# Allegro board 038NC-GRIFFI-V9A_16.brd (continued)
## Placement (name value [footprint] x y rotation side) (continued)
UNK1TP_SDA  TP01  [TP_040_T]  19.67 330.46 0 top
UNK1TP_SHPHLD_F  TP01  [TP_040_T]  19.11 298.48 270 top
UNK1TP_SHPHLD_S  TP01  [TP_040_T]  19.11 295.94 90 top
UNK1TP_SW_F  TP01  [TP_040_T]  36.07 330.46 0 top
UNK1TP_SW_S  TP01  [TP_040_T]  33.53 330.46 0 top
UNK1TP_VBAT_F  TP01  [TP_040_T]  42.06 287.14 0 top
UNK1TP_VBAT_S  TP01  [TP_040_T]  38.86 287.14 0 top
UNK1TP_VBUS_F  TP01  [TP_040_T]  23.37 330.46 0 top
UNK1TP_VBUS_S  TP01  [TP_040_T]  25.91 330.46 0 top
UNK1TP_VDDIO_F  TP01  [TP_040_T]  38.61 335.54 0 top
UNK1TP_VDDIO_S  TP01  [TP_040_T]  125.91 486.88 0 top
UNK1TP_VEST  TP01  [TP_040_T]  13.28 269.26 0 top
UNK1TP_VOUT_F  TP01  [TP_040_T]  127.89 486.88 0 top
UNK1TP_VOUT_S  TP01  [TP_040_T]  38.61 330.46 0 top
UNK1TP_VSYS_F  TP01  [TP_040_T]  25.91 335.54 0 top
UNK1TP_VSYS_S  TP01  [TP_040_T]  23.37 335.54 0 top
UNK1U1  ADR4550BRZ-SOIC8  [SO8_195X127MM]  36.83 296.98 180 bottom
UNK2C1  1U-6.3-X7R-S6-MU  [C0603]  19.36 142.49 90 bottom
UNK2C2  2.2U-25-X8R-SA-TDK  [C1206]  35.84 178.21 180 bottom
UNK2C3  10U-6.3-X7R-S6-SS  [C0603]  31.92 177.36 270 bottom
UNK2C4  2.2U-25-X8R-SA-TDK  [C1206]  28.38 192.05 180 bottom
UNK2C5  2.2U-25-X8R-SA-TDK  [C1206]  22.68 192.05 0 bottom
UNK2C6  4.7U-6.3-X-S6  [C0603]  41.21 178.21 180 bottom
UNK2C7  0.1U-25-X7R-S6-YA  [C0603]  41.75 238.65 0 bottom
UNK2C8  1U-50-X7R-S6-TY  [C0603]  41.75 237.13 0 bottom
UNK2C9  0.1U-25-X7R-S6-YA  [C0603]  31.9 237.3 270 bottom
UNK2C12  2.2U-25-X8R-SA-TDK  [C1206]  26.98 142.89 90 bottom
UNK2CS1  CNC-S4  [C0402]  22.12 211.3 180 bottom
UNK2CS4  CNC-S4  [C0402]  22.12 207.49 0 bottom
UNK2CS5  CNC-S4  [C0402]  22.12 206.22 0 bottom
UNK2CS19  CNC-S4  [C0402]  35.85 207.02 0 bottom
UNK2CS20  CNC-S4  [C0402]  35.85 208.29 0 bottom
UNK2CS21  CNC-S4  [C0402]  35.85 209.56 0 bottom
UNK2CS22  CNC-S4  [C0402]  33.2 213.05 90 bottom
UNK2CS23  CNC-S4  [C0402]  31.93 213.05 90 bottom
UNK2CS25  CNC-S4  [C0402]  28.12 213.05 90 bottom
UNK2CS26  CNC-S4  [C0402]  26.85 213.05 270 bottom
UNK2CS27  CNC-S4  [C0402]  25.58 213.05 270 bottom
UNK2CS28  CNC-S4  [C0402]  24.31 213.05 90 bottom
UNK2K1  UA2-12NJ-V2  [RL_NECUA2_12V_V2]  33 185.33 90 bottom
UNK2K2  UA2-12NJ-V2  [RL_NECUA2_12V_V2]  25.53 185.33 90 bottom
UNK2K3  UA2-12NJ-V2  [RL_NECUA2_12V_V2]  16.66 207.46 270 bottom
UNK2K4  UA2-12NJ-V2  [RL_NECUA2_12V_V2]  25.53 169.7 90 bottom
UNK2K5  UA2-12NJ-V2  [RL_NECUA2_12V_V2]  18.07 169.7 90 bottom
UNK2K6  UA2-12NJ-V2  [RL_NECUA2_12V_V2]  33 169.3 270 bottom
UNK2K7  UA2-12NJ-V2  [RL_NECUA2_12V_V2]  40.46 169.7 90 bottom
UNK2K8  UA2-12NJ-V2  [RL_NECUA2_12V_V2]  18.07 185.33 90 bottom
UNK2K9  UA2-12NJ-V2  [RL_NECUA2_12V_V2]  40.46 142.72 270 bottom
UNK2K10  UA2-12NJ-V2  [RL_NECUA2_12V_V2]  40.46 185.33 90 bottom
UNK2K11  UA2-12NJ-V2  [RL_NECUA2_12V_V2]  33 229.98 90 bottom
UNK2K12  UA2-12NJ-V2  [RL_NECUA2_12V_V2]  40.46 229.98 90 bottom
UNK2K13  UA2-12NJ-V2  [RL_NECUA2_12V_V2]  18.07 229.58 270 bottom
UNK2K14  UA2-12NJ-V2  [RL_NECUA2_12V_V2]  25.53 229.58 270 bottom
UNK2R1  4.7K-1-S4-WA  [R0402]  16.51 201.49 180 bottom
UNK2R2  3.01K-0.1-S4-PAN  [R0402]  21.8 166.2 90 bottom
UNK2R3  10K-0.1-S4  [R0402]  29.26 172.8 270 bottom
UNK2R7  1K-1-S4  [R0402]  41.78 149.43 0 bottom
UNK2R8  1K-1-S4  [R0402]  39.14 149.43 180 bottom
UNK2R13  0-5-S4  [R0402]  164.24 484.56 0 top
UNK2R14  0-5-S4  [R0402]  166.44 484.56 0 top
UNK2R41  24K-0.1-S4  [R0402]  44.26 166.2 90 bottom
UNK2R42  44.2K-0.1-S4-PAN  [R0402]  44.26 168.4 90 bottom
UNK2RS1  0-5-S4  [R0402]  22.12 208.76 0 bottom
UNK2RS2  NC/0-5-S4  [R0402]  29.39 213.05 270 bottom
UNK2RS3  NC/0-5-S4  [R0402]  22.12 210.03 0 bottom
UNK2RS4  0-5-S4  [R0402]  30.66 213.05 270 bottom
UNK2RS5  0-5-S4  [R0402]  30.02 214.7 0 bottom
UNK2SH2  SHORT  [DEFAULT_SHORT_SMALL]  87.13 483.17 0 top
UNK2SH7  SHORT  [DEFAULT_SHORT_SMALL]  117.97 483.17 0 top
UNK2SH9  SHORT  [DEFAULT_SHORT_SMALL]  120.18 483.17 0 top
UNK2SH14  SHORT  [DEFAULT_SHORT_SMALL]  82.72 483.17 0 top
UNK2SH16  SHORT  [DEFAULT_SHORT_SMALL]  84.92 483.17 0 top
UNK2SH20  SHORT  [DEFAULT_SHORT_SMALL]  89.33 483.17 0 top
UNK2SH29  SHORT  [DEFAULT_SHORT_SMALL]  91.53 483.17 0 top
UNK2SH30  SHORT  [DEFAULT_SHORT_SMALL]  93.74 483.17 0 top
UNK2SH32  SHORT  [DEFAULT_SHORT_SMALL]  95.94 483.17 0 top
UNK2SH33  SHORT  [DEFAULT_SHORT_SMALL]  98.14 483.17 0 top
UNK2SH34  SHORT  [DEFAULT_SHORT_SMALL]  100.35 483.17 0 top
UNK2SH35  SHORT  [DEFAULT_SHORT_SMALL]  102.55 483.17 0 top
UNK2SH36  SHORT  [DEFAULT_SHORT_SMALL]  104.75 483.17 0 top
UNK2SH37  SHORT  [DEFAULT_SHORT_SMALL]  106.96 483.17 0 top
UNK2SH38  SHORT  [DEFAULT_SHORT_SMALL]  109.16 483.17 0 top
UNK2SH39  SHORT  [DEFAULT_SHORT_SMALL]  111.36 483.17 0 top
UNK2SH40  SHORT  [DEFAULT_SHORT_SMALL]  113.57 483.17 0 top
UNK2SH41  SHORT  [DEFAULT_SHORT_SMALL]  115.77 483.17 0 top
UNK2TP_AVSS2/TST  TP01  [TP_040_T]  13.84 214.45 0 top
UNK2TP_GPIO0  TP01  [TP_040_T]  29.17 178.59 270 top
UNK2TP_GPIO1  TP01  [TP_040_T]  29.17 176.05 90 top
UNK2TP_GPIO2  TP01  [TP_040_T]  16.47 178.59 180 top
UNK2TP_GPIO3  TP01  [TP_040_T]  16.47 176.05 90 top
UNK2TP_GPIO4  TP01  [TP_040_T]  19.01 178.59 90 top
UNK2TP_LED0  TP01  [TP_040_T]  21.55 176.05 90 top
UNK2TP_LED1  TP01  [TP_040_T]  21.55 178.59 270 top
UNK2TP_LED2  TP01  [TP_040_T]  19.01 176.05 90 top
UNK2TP_LSIN1_F  TP01  [TP_040_T]  26.98 146.72 180 top
UNK2TP_LSIN1_G  TP01  [TP_040_T]  22.89 486.88 0 top
UNK2TP_LSIN1_S  TP01  [TP_040_T]  29.52 146.72 180 top
UNK2TP_LSIN2/NCHGEN_F  TP01  [TP_040_T]  26.98 141.64 180 top
UNK2TP_LSIN2/NCHGEN_G  TP01  [TP_040_T]  24.87 486.88 0 top
UNK2TP_LSIN2/NCHGEN_S  TP01  [TP_040_T]  29.52 141.64 180 top
UNK2TP_LSOUT1_F  TP01  [TP_040_T]  26.85 486.88 0 top
UNK2TP_LSOUT1_G  TP01  [TP_040_T]  28.83 486.88 0 top
UNK2TP_LSOUT1_S  TP01  [TP_040_T]  24.09 176.05 90 top
UNK2TP_LSOUT2/SUSPEND1_G  TP01  [TP_040_T]  30.81 486.88 0 top
UNK2TP_LSOUT2/SUSPEND1_S  TP01  [TP_040_T]  24.09 178.59 180 top
UNK2TP_LSOUT2/SUSPEND_F  TP01  [TP_040_T]  32.79 486.88 0 top
UNK2TP_NCHG/ATB0_F  TP01  [TP_040_T]  23.93 233.58 0 top
UNK2TP_NCHG/ATB0_G  TP01  [TP_040_T]  23.93 229.18 0 top
UNK2TP_NCHG/ATB0_S  TP01  [TP_040_T]  27.13 231.38 0 top
UNK2TP_NPG/ATB1_F  TP01  [TP_040_T]  16.47 233.58 0 top
UNK2TP_NPG/ATB1_G  TP01  [TP_040_T]  16.47 229.18 0 top
UNK2TP_NPG/ATB1_S  TP01  [TP_040_T]  19.67 233.58 0 top
UNK2TP_NTC  TP01  [TP_040_T]  27.13 167.9 0 top
UNK2TP_REF_5V  TP01  [TP_040_T]  34.77 486.88 0 top
UNK2TP_SCL  TP01  [TP_040_T]  42.06 144.52 180 top
UNK2TP_SDA  TP01  [TP_040_T]  38.86 144.52 180 top
UNK2TP_SHPHLD_F  TP01  [TP_040_T]  26.63 176.05 90 top
UNK2TP_SHPHLD_S  TP01  [TP_040_T]  26.63 178.59 270 top
UNK2TP_SW_F  TP01  [TP_040_T]  21.9 146.72 180 top
UNK2TP_SW_S  TP01  [TP_040_T]  24.44 146.72 180 top
UNK2TP_VBAT_F  TP01  [TP_040_T]  42.06 228.18 0 top
UNK2TP_VBAT_S  TP01  [TP_040_T]  38.86 228.18 0 top
UNK2TP_VBUS_F  TP01  [TP_040_T]  34.6 146.72 180 top
UNK2TP_VBUS_S  TP01  [TP_040_T]  32.06 146.72 180 top
UNK2TP_VDDIO_F  TP01  [TP_040_T]  19.36 141.64 180 top
UNK2TP_VDDIO_S  TP01  [TP_040_T]  16.82 141.64 180 top
UNK2TP_VEST  TP01  [TP_040_T]  13.28 209.26 0 top
UNK2TP_VOUT_F  TP01  [TP_040_T]  16.82 146.72 180 top
UNK2TP_VOUT_S  TP01  [TP_040_T]  19.36 146.72 180 top
UNK2TP_VSYS_F  TP01  [TP_040_T]  32.06 141.64 180 top
UNK2TP_VSYS_S  TP01  [TP_040_T]  34.6 141.64 180 top
UNK2U1  ADR4550BRZ-SOIC8  [SO8_195X127MM]  36.32 238.02 180 bottom
UNK3C1  1U-6.3-X7R-S6-MU  [C0603]  68.61 334.69 270 bottom
UNK3C2  2.2U-25-X8R-SA-TDK  [C1206]  59.52 237.92 90 bottom
UNK3C3  10U-6.3-X7R-S6-SS  [C0603]  57.13 238.61 270 bottom
UNK3C4  2.2U-25-X8R-SA-TDK  [C1206]  49.67 237.92 90 bottom
UNK3C5  2.2U-25-X8R-SA-TDK  [C1206]  46.47 237.92 270 bottom
UNK3C6  4.7U-6.3-X-S6  [C0603]  74.26 241.42 270 bottom
UNK3C7  0.1U-25-X7R-S6-YA  [C0603]  72.25 297.61 0 bottom
UNK3C8  1U-50-X7R-S6-TY  [C0603]  72.25 296.09 0 bottom
UNK3C9  0.1U-25-X7R-S6-YA  [C0603]  62.41 296.26 270 bottom
UNK3C12  2.2U-25-X8R-SA-TDK  [C1206]  60.99 334.29 270 bottom
UNK3CS1  CNC-S4  [C0402]  52.12 271.3 180 bottom
UNK3CS4  CNC-S4  [C0402]  52.12 267.49 0 bottom
UNK3CS5  CNC-S4  [C0402]  52.12 266.22 0 bottom
UNK3CS19  CNC-S4  [C0402]  65.85 267.02 0 bottom
UNK3CS20  CNC-S4  [C0402]  65.85 268.29 0 bottom
UNK3CS21  CNC-S4  [C0402]  65.85 269.56 0 bottom
UNK3CS22  CNC-S4  [C0402]  63.2 273.05 90 bottom
UNK3CS23  CNC-S4  [C0402]  61.93 273.05 90 bottom
UNK3CS25  CNC-S4  [C0402]  58.12 273.05 90 bottom
UNK3CS26  CNC-S4  [C0402]  56.85 273.05 270 bottom
UNK3CS27  CNC-S4  [C0402]  55.58 273.05 270 bottom
UNK3CS28  CNC-S4  [C0402]  54.31 273.05 90 bottom
UNK3K1  UA2-12NJ-V2  [RL_NECUA2_12V_V2]  63 246.27 90 bottom
UNK3K2  UA2-12NJ-V2  [RL_NECUA2_12V_V2]  55.53 246.27 90 bottom
UNK3K3  UA2-12NJ-V2  [RL_NECUA2_12V_V2]  46.66 267.46 270 bottom
UNK3K4  UA2-12NJ-V2  [RL_NECUA2_12V_V2]  63 305.28 270 bottom
UNK3K5  UA2-12NJ-V2  [RL_NECUA2_12V_V2]  70.46 305.28 270 bottom
UNK3K6  UA2-12NJ-V2  [RL_NECUA2_12V_V2]  55.53 305.68 90 bottom
UNK3K7  UA2-12NJ-V2  [RL_NECUA2_12V_V2]  48.07 305.28 270 bottom
UNK3K8  UA2-12NJ-V2  [RL_NECUA2_12V_V2]  48.07 246.27 90 bottom
UNK3K9  UA2-12NJ-V2  [RL_NECUA2_12V_V2]  48.07 332.26 90 bottom
UNK3K10  UA2-12NJ-V2  [RL_NECUA2_12V_V2]  63 288.94 90 bottom
UNK3K11  UA2-12NJ-V2  [RL_NECUA2_12V_V2]  70.46 246.27 90 bottom
UNK3K12  UA2-12NJ-V2  [RL_NECUA2_12V_V2]  70.46 288.94 90 bottom
UNK3K13  UA2-12NJ-V2  [RL_NECUA2_12V_V2]  48.07 288.54 270 bottom
UNK3K14  UA2-12NJ-V2  [RL_NECUA2_12V_V2]  55.53 288.54 270 bottom
UNK3R1  4.7K-1-S4-WA  [R0402]  46.51 261.49 180 bottom
UNK3R2  3.01K-0.1-S4-PAN  [R0402]  66.73 308.78 270 bottom
UNK3R3  10K-0.1-S4  [R0402]  59.26 301.18 270 bottom
UNK3R7  1K-1-S4  [R0402]  46.75 325.55 180 bottom
UNK3R8  1K-1-S4  [R0402]  49.39 325.55 0 bottom
UNK3R13  0-5-S4  [R0402]  168.65 484.56 0 top
UNK3R14  0-5-S4  [R0402]  170.85 484.56 0 top
UNK3R41  24K-0.1-S4  [R0402]  44.26 308.78 270 bottom
UNK3R42  44.2K-0.1-S4-PAN  [R0402]  44.26 306.58 270 bottom
UNK3RS1  0-5-S4  [R0402]  52.12 268.76 0 bottom
UNK3RS2  NC/0-5-S4  [R0402]  59.39 273.05 270 bottom
UNK3RS3  NC/0-5-S4  [R0402]  52.12 270.03 0 bottom
UNK3RS4  0-5-S4  [R0402]  60.66 273.05 270 bottom
UNK3RS5  0-5-S4  [R0402]  60.02 274.7 0 bottom
UNK3SH2  SHORT  [DEFAULT_SHORT_SMALL]  126.79 483.17 0 top
UNK3SH7  SHORT  [DEFAULT_SHORT_SMALL]  157.63 483.17 0 top
UNK3SH9  SHORT  [DEFAULT_SHORT_SMALL]  159.83 483.17 0 top
UNK3SH14  SHORT  [DEFAULT_SHORT_SMALL]  122.38 483.17 0 top
UNK3SH16  SHORT  [DEFAULT_SHORT_SMALL]  124.58 483.17 0 top
UNK3SH20  SHORT  [DEFAULT_SHORT_SMALL]  128.99 483.17 0 top
UNK3SH29  SHORT  [DEFAULT_SHORT_SMALL]  131.19 483.17 0 top
UNK3SH30  SHORT  [DEFAULT_SHORT_SMALL]  133.39 483.17 0 top
UNK3SH32  SHORT  [DEFAULT_SHORT_SMALL]  135.6 483.17 0 top
UNK3SH33  SHORT  [DEFAULT_SHORT_SMALL]  137.8 483.17 0 top
UNK3SH34  SHORT  [DEFAULT_SHORT_SMALL]  140 483.17 0 top
UNK3SH35  SHORT  [DEFAULT_SHORT_SMALL]  142.21 483.17 0 top
UNK3SH36  SHORT  [DEFAULT_SHORT_SMALL]  144.41 483.17 0 top
UNK3SH37  SHORT  [DEFAULT_SHORT_SMALL]  146.61 483.17 0 top
UNK3SH38  SHORT  [DEFAULT_SHORT_SMALL]  148.82 483.17 0 top
UNK3SH39  SHORT  [DEFAULT_SHORT_SMALL]  151.02 483.17 0 top
UNK3SH40  SHORT  [DEFAULT_SHORT_SMALL]  153.22 483.17 0 top
UNK3SH41  SHORT  [DEFAULT_SHORT_SMALL]  155.43 483.17 0 top
UNK3TP_AVSS2/TST  TP01  [TP_040_T]  43.84 274.45 0 top
UNK3TP_GPIO0  TP01  [TP_040_T]  46.57 295.94 90 top
UNK3TP_GPIO1  TP01  [TP_040_T]  46.57 298.48 270 top
UNK3TP_GPIO2  TP01  [TP_040_T]  59.27 295.94 0 top
UNK3TP_GPIO3  TP01  [TP_040_T]  59.27 298.48 270 top
UNK3TP_GPIO4  TP01  [TP_040_T]  56.73 295.94 270 top
UNK3TP_LED0  TP01  [TP_040_T]  54.19 298.48 270 top
UNK3TP_LED1  TP01  [TP_040_T]  54.19 295.94 90 top
UNK3TP_LED2  TP01  [TP_040_T]  56.73 298.48 270 top
UNK3TP_LSIN1_F  TP01  [TP_040_T]  60.99 330.46 0 top
UNK3TP_LSIN1_G  TP01  [TP_040_T]  36.75 486.88 0 top
UNK3TP_LSIN1_S  TP01  [TP_040_T]  58.45 330.46 0 top
UNK3TP_LSIN2/NCHGEN_F  TP01  [TP_040_T]  60.99 335.54 0 top
UNK3TP_LSIN2/NCHGEN_G  TP01  [TP_040_T]  38.74 486.88 0 top
UNK3TP_LSIN2/NCHGEN_S  TP01  [TP_040_T]  58.45 335.54 0 top
UNK3TP_LSOUT1_F  TP01  [TP_040_T]  49.67 244.47 180 top
UNK3TP_LSOUT1_G  TP01  [TP_040_T]  40.72 486.88 0 top
UNK3TP_LSOUT1_S  TP01  [TP_040_T]  51.65 298.48 270 top
UNK3TP_LSOUT2/SUSPEND1_G  TP01  [TP_040_T]  42.7 486.88 0 top
UNK3TP_LSOUT2/SUSPEND1_S  TP01  [TP_040_T]  51.65 295.94 0 top
UNK3TP_LSOUT2/SUSPEND_F  TP01  [TP_040_T]  68.86 244.47 180 top
UNK3TP_NCHG/ATB0_F  TP01  [TP_040_T]  53.93 292.54 0 top
UNK3TP_NCHG/ATB0_G  TP01  [TP_040_T]  53.93 288.14 0 top
UNK3TP_NCHG/ATB0_S  TP01  [TP_040_T]  57.13 290.34 0 top
UNK3TP_NPG/ATB1_F  TP01  [TP_040_T]  46.47 292.54 0 top
UNK3TP_NPG/ATB1_G  TP01  [TP_040_T]  46.47 288.14 0 top
UNK3TP_NPG/ATB1_S  TP01  [TP_040_T]  49.67 292.54 0 top
UNK3TP_NTC  TP01  [TP_040_T]  61.4 307.08 180 top
UNK3TP_REF_5V  TP01  [TP_040_T]  64.59 242.27 180 top
UNK3TP_SCL  TP01  [TP_040_T]  46.47 330.46 0 top
UNK3TP_SDA  TP01  [TP_040_T]  49.67 330.46 0 top
UNK3TP_SHPHLD_F  TP01  [TP_040_T]  49.11 298.48 270 top
UNK3TP_SHPHLD_S  TP01  [TP_040_T]  49.11 295.94 90 top
UNK3TP_SW_F  TP01  [TP_040_T]  66.07 330.46 0 top
UNK3TP_SW_S  TP01  [TP_040_T]  63.53 330.46 0 top
UNK3TP_VBAT_F  TP01  [TP_040_T]  72.06 287.14 0 top
UNK3TP_VBAT_S  TP01  [TP_040_T]  68.86 287.14 0 top
UNK3TP_VBUS_F  TP01  [TP_040_T]  53.37 330.46 0 top
UNK3TP_VBUS_S  TP01  [TP_040_T]  55.91 330.46 0 top
UNK3TP_VDDIO_F  TP01  [TP_040_T]  68.61 335.54 0 top
UNK3TP_VDDIO_S  TP01  [TP_040_T]  44.68 486.88 0 top
UNK3TP_VEST  TP01  [TP_040_T]  43.28 269.26 0 top
UNK3TP_VOUT_F  TP01  [TP_040_T]  46.66 486.88 0 top
UNK3TP_VOUT_S  TP01  [TP_040_T]  68.61 330.46 0 top
UNK3TP_VSYS_F  TP01  [TP_040_T]  55.91 335.54 0 top
UNK3TP_VSYS_S  TP01  [TP_040_T]  53.37 335.54 0 top
UNK3U1  ADR4550BRZ-SOIC8  [SO8_195X127MM]  66.83 296.98 180 bottom
UNK4C1  1U-6.3-X7R-S6-MU  [C0603]  49.36 142.49 90 bottom
UNK4C2  2.2U-25-X8R-SA-TDK  [C1206]  65.84 178.21 180 bottom
UNK4C3  10U-6.3-X7R-S6-SS  [C0603]  61.92 177.36 270 bottom
UNK4C4  2.2U-25-X8R-SA-TDK  [C1206]  58.38 192.05 180 bottom
UNK4C5  2.2U-25-X8R-SA-TDK  [C1206]  52.68 192.05 0 bottom
UNK4C6  4.7U-6.3-X-S6  [C0603]  71.21 178.21 180 bottom
UNK4C7  0.1U-25-X7R-S6-YA  [C0603]  71.75 238.65 0 bottom
UNK4C8  1U-50-X7R-S6-TY  [C0603]  71.75 237.13 0 bottom
UNK4C9  0.1U-25-X7R-S6-YA  [C0603]  61.9 237.3 270 bottom
UNK4C12  2.2U-25-X8R-SA-TDK  [C1206]  56.98 142.89 90 bottom
UNK4CS1  CNC-S4  [C0402]  52.12 211.3 180 bottom
UNK4CS4  CNC-S4  [C0402]  52.12 207.49 0 bottom
UNK4CS5  CNC-S4  [C0402]  52.12 206.22 0 bottom
UNK4CS19  CNC-S4  [C0402]  65.85 207.02 0 bottom
UNK4CS20  CNC-S4  [C0402]  65.85 208.29 0 bottom
UNK4CS21  CNC-S4  [C0402]  65.85 209.56 0 bottom
UNK4CS22  CNC-S4  [C0402]  63.2 213.05 90 bottom
UNK4CS23  CNC-S4  [C0402]  61.93 213.05 90 bottom
UNK4CS25  CNC-S4  [C0402]  58.12 213.05 90 bottom
UNK4CS26  CNC-S4  [C0402]  56.85 213.05 270 bottom
UNK4CS27  CNC-S4  [C0402]  55.58 213.05 270 bottom
UNK4CS28  CNC-S4  [C0402]  54.31 213.05 90 bottom
UNK4K1  UA2-12NJ-V2  [RL_NECUA2_12V_V2]  63 185.33 90 bottom
UNK4K2  UA2-12NJ-V2  [RL_NECUA2_12V_V2]  55.53 185.33 90 bottom
UNK4K3  UA2-12NJ-V2  [RL_NECUA2_12V_V2]  46.66 207.46 270 bottom
UNK4K4  UA2-12NJ-V2  [RL_NECUA2_12V_V2]  55.53 169.7 90 bottom
UNK4K5  UA2-12NJ-V2  [RL_NECUA2_12V_V2]  48.07 169.7 90 bottom
UNK4K6  UA2-12NJ-V2  [RL_NECUA2_12V_V2]  63 169.3 270 bottom
UNK4K7  UA2-12NJ-V2  [RL_NECUA2_12V_V2]  70.46 169.7 90 bottom
UNK4K8  UA2-12NJ-V2  [RL_NECUA2_12V_V2]  48.07 185.33 90 bottom
UNK4K9  UA2-12NJ-V2  [RL_NECUA2_12V_V2]  70.46 142.72 270 bottom
UNK4K10  UA2-12NJ-V2  [RL_NECUA2_12V_V2]  70.46 185.33 90 bottom
UNK4K11  UA2-12NJ-V2  [RL_NECUA2_12V_V2]  63 229.98 90 bottom
UNK4K12  UA2-12NJ-V2  [RL_NECUA2_12V_V2]  70.46 229.98 90 bottom
UNK4K13  UA2-12NJ-V2  [RL_NECUA2_12V_V2]  48.07 229.58 270 bottom
UNK4K14  UA2-12NJ-V2  [RL_NECUA2_12V_V2]  55.53 229.58 270 bottom
UNK4R1  4.7K-1-S4-WA  [R0402]  46.51 201.49 180 bottom
UNK4R2  3.01K-0.1-S4-PAN  [R0402]  51.8 166.2 90 bottom
UNK4R3  10K-0.1-S4  [R0402]  59.26 172.8 270 bottom
UNK4R7  1K-1-S4  [R0402]  71.78 149.43 0 bottom
UNK4R8  1K-1-S4  [R0402]  69.14 149.43 180 bottom
UNK4R13  0-5-S4  [R0402]  173.05 484.56 0 top
UNK4R14  0-5-S4  [R0402]  175.26 484.56 0 top
UNK4R41  24K-0.1-S4  [R0402]  74.26 166.2 90 bottom
UNK4R42  44.2K-0.1-S4-PAN  [R0402]  74.26 168.4 90 bottom
UNK4RS1  0-5-S4  [R0402]  52.12 208.76 0 bottom
UNK4RS2  NC/0-5-S4  [R0402]  59.39 213.05 270 bottom
UNK4RS3  NC/0-5-S4  [R0402]  52.12 210.03 0 bottom
UNK4RS4  0-5-S4  [R0402]  60.66 213.05 270 bottom
UNK4RS5  0-5-S4  [R0402]  60.02 214.7 0 bottom
UNK4SH2  SHORT  [DEFAULT_SHORT_SMALL]  166.44 483.17 0 top
UNK4SH7  SHORT  [DEFAULT_SHORT_SMALL]  197.29 483.17 0 top
UNK4SH9  SHORT  [DEFAULT_SHORT_SMALL]  199.49 483.17 0 top
UNK4SH14  SHORT  [DEFAULT_SHORT_SMALL]  162.04 483.17 0 top
UNK4SH16  SHORT  [DEFAULT_SHORT_SMALL]  164.24 483.17 0 top
UNK4SH20  SHORT  [DEFAULT_SHORT_SMALL]  168.65 483.17 0 top
UNK4SH29  SHORT  [DEFAULT_SHORT_SMALL]  170.85 483.17 0 top
UNK4SH30  SHORT  [DEFAULT_SHORT_SMALL]  173.05 483.17 0 top
UNK4SH32  SHORT  [DEFAULT_SHORT_SMALL]  175.26 483.17 0 top
UNK4SH33  SHORT  [DEFAULT_SHORT_SMALL]  177.46 483.17 0 top
UNK4SH34  SHORT  [DEFAULT_SHORT_SMALL]  179.66 483.17 0 top
UNK4SH35  SHORT  [DEFAULT_SHORT_SMALL]  181.87 483.17 0 top
UNK4SH36  SHORT  [DEFAULT_SHORT_SMALL]  184.07 483.17 0 top
UNK4SH37  SHORT  [DEFAULT_SHORT_SMALL]  186.27 483.17 0 top
UNK4SH38  SHORT  [DEFAULT_SHORT_SMALL]  188.47 483.17 0 top
UNK4SH39  SHORT  [DEFAULT_SHORT_SMALL]  190.68 483.17 0 top
UNK4SH40  SHORT  [DEFAULT_SHORT_SMALL]  192.88 483.17 0 top
UNK4SH41  SHORT  [DEFAULT_SHORT_SMALL]  195.08 483.17 0 top
UNK4TP_AVSS2/TST  TP01  [TP_040_T]  43.84 214.45 0 top
UNK4TP_GPIO0  TP01  [TP_040_T]  59.17 178.59 270 top
UNK4TP_GPIO1  TP01  [TP_040_T]  59.17 176.05 90 top
UNK4TP_GPIO2  TP01  [TP_040_T]  46.47 178.59 180 top
UNK4TP_GPIO3  TP01  [TP_040_T]  46.47 176.05 90 top
UNK4TP_GPIO4  TP01  [TP_040_T]  49.01 178.59 90 top
UNK4TP_LED0  TP01  [TP_040_T]  51.55 176.05 90 top
UNK4TP_LED1  TP01  [TP_040_T]  51.55 178.59 270 top
UNK4TP_LED2  TP01  [TP_040_T]  49.01 176.05 90 top
UNK4TP_LSIN1_F  TP01  [TP_040_T]  56.98 146.72 180 top
UNK4TP_LSIN1_G  TP01  [TP_040_T]  48.64 486.88 0 top
UNK4TP_LSIN1_S  TP01  [TP_040_T]  59.52 146.72 180 top
UNK4TP_LSIN2/NCHGEN_F  TP01  [TP_040_T]  56.98 141.64 180 top
UNK4TP_LSIN2/NCHGEN_G  TP01  [TP_040_T]  50.62 486.88 0 top
UNK4TP_LSIN2/NCHGEN_S  TP01  [TP_040_T]  59.52 141.64 180 top
UNK4TP_LSOUT1_F  TP01  [TP_040_T]  52.6 486.88 0 top
UNK4TP_LSOUT1_G  TP01  [TP_040_T]  54.58 486.88 0 top
UNK4TP_LSOUT1_S  TP01  [TP_040_T]  54.09 176.05 90 top
UNK4TP_LSOUT2/SUSPEND1_G  TP01  [TP_040_T]  56.57 486.88 0 top
UNK4TP_LSOUT2/SUSPEND1_S  TP01  [TP_040_T]  54.09 178.59 180 top
UNK4TP_LSOUT2/SUSPEND_F  TP01  [TP_040_T]  58.55 486.88 0 top
UNK4TP_NCHG/ATB0_F  TP01  [TP_040_T]  53.93 233.58 0 top
UNK4TP_NCHG/ATB0_G  TP01  [TP_040_T]  53.93 229.18 0 top
UNK4TP_NCHG/ATB0_S  TP01  [TP_040_T]  57.13 231.38 0 top
UNK4TP_NPG/ATB1_F  TP01  [TP_040_T]  46.47 233.58 0 top
UNK4TP_NPG/ATB1_G  TP01  [TP_040_T]  46.47 229.18 0 top
UNK4TP_NPG/ATB1_S  TP01  [TP_040_T]  49.67 233.58 0 top
UNK4TP_NTC  TP01  [TP_040_T]  57.13 167.9 0 top
UNK4TP_REF_5V  TP01  [TP_040_T]  60.53 486.88 0 top
UNK4TP_SCL  TP01  [TP_040_T]  72.06 144.52 180 top
UNK4TP_SDA  TP01  [TP_040_T]  68.86 144.52 180 top
UNK4TP_SHPHLD_F  TP01  [TP_040_T]  56.63 176.05 90 top
UNK4TP_SHPHLD_S  TP01  [TP_040_T]  56.63 178.59 270 top
UNK4TP_SW_F  TP01  [TP_040_T]  51.9 146.72 180 top
UNK4TP_SW_S  TP01  [TP_040_T]  54.44 146.72 180 top
UNK4TP_VBAT_F  TP01  [TP_040_T]  72.06 228.18 0 top
UNK4TP_VBAT_S  TP01  [TP_040_T]  68.86 228.18 0 top
UNK4TP_VBUS_F  TP01  [TP_040_T]  64.6 146.72 180 top
UNK4TP_VBUS_S  TP01  [TP_040_T]  62.06 146.72 180 top
UNK4TP_VDDIO_F  TP01  [TP_040_T]  49.36 141.64 180 top
UNK4TP_VDDIO_S  TP01  [TP_040_T]  46.82 141.64 180 top
UNK4TP_VEST  TP01  [TP_040_T]  43.28 209.26 0 top
UNK4TP_VOUT_F  TP01  [TP_040_T]  46.82 146.72 180 top
UNK4TP_VOUT_S  TP01  [TP_040_T]  49.36 146.72 180 top
UNK4TP_VSYS_F  TP01  [TP_040_T]  62.06 141.64 180 top
UNK4TP_VSYS_S  TP01  [TP_040_T]  64.6 141.64 180 top
UNK4U1  ADR4550BRZ-SOIC8  [SO8_195X127MM]  66.32 238.02 180 bottom
UNK5C1  1U-6.3-X7R-S6-MU  [C0603]  98.61 334.69 270 bottom
UNK5C2  2.2U-25-X8R-SA-TDK  [C1206]  89.52 237.92 90 bottom
UNK5C3  10U-6.3-X7R-S6-SS  [C0603]  87.13 238.61 270 bottom
UNK5C4  2.2U-25-X8R-SA-TDK  [C1206]  79.67 237.92 90 bottom
UNK5C5  2.2U-25-X8R-SA-TDK  [C1206]  76.47 237.92 270 bottom
UNK5C6  4.7U-6.3-X-S6  [C0603]  104.26 241.42 270 bottom
UNK5C7  0.1U-25-X7R-S6-YA  [C0603]  102.25 297.61 0 bottom
UNK5C8  1U-50-X7R-S6-TY  [C0603]  102.25 296.09 0 bottom
UNK5C9  0.1U-25-X7R-S6-YA  [C0603]  92.41 296.26 270 bottom
UNK5C12  2.2U-25-X8R-SA-TDK  [C1206]  90.99 334.29 270 bottom
UNK5CS1  CNC-S4  [C0402]  82.12 271.3 180 bottom
UNK5CS4  CNC-S4  [C0402]  82.12 267.49 0 bottom
UNK5CS5  CNC-S4  [C0402]  82.12 266.22 0 bottom
UNK5CS19  CNC-S4  [C0402]  95.85 267.02 0 bottom
UNK5CS20  CNC-S4  [C0402]  95.85 268.29 0 bottom
UNK5CS21  CNC-S4  [C0402]  95.85 269.56 0 bottom
UNK5CS22  CNC-S4  [C0402]  93.2 273.05 90 bottom
UNK5CS23  CNC-S4  [C0402]  91.93 273.05 90 bottom
UNK5CS25  CNC-S4  [C0402]  88.12 273.05 90 bottom
UNK5CS26  CNC-S4  [C0402]  86.85 273.05 270 bottom
UNK5CS27  CNC-S4  [C0402]  85.58 273.05 270 bottom
UNK5CS28  CNC-S4  [C0402]  84.31 273.05 90 bottom
UNK5K1  UA2-12NJ-V2  [RL_NECUA2_12V_V2]  92.99 246.27 90 bottom
UNK5K2  UA2-12NJ-V2  [RL_NECUA2_12V_V2]  85.53 246.27 90 bottom
UNK5K3  UA2-12NJ-V2  [RL_NECUA2_12V_V2]  76.66 267.46 270 bottom
UNK5K4  UA2-12NJ-V2  [RL_NECUA2_12V_V2]  92.99 305.28 270 bottom
UNK5K5  UA2-12NJ-V2  [RL_NECUA2_12V_V2]  100.46 305.28 270 bottom
UNK5K6  UA2-12NJ-V2  [RL_NECUA2_12V_V2]  85.53 305.68 90 bottom
UNK5K7  UA2-12NJ-V2  [RL_NECUA2_12V_V2]  78.07 305.28 270 bottom
UNK5K8  UA2-12NJ-V2  [RL_NECUA2_12V_V2]  78.07 246.27 90 bottom
UNK5K9  UA2-12NJ-V2  [RL_NECUA2_12V_V2]  78.07 332.26 90 bottom
UNK5K10  UA2-12NJ-V2  [RL_NECUA2_12V_V2]  92.99 288.94 90 bottom
UNK5K11  UA2-12NJ-V2  [RL_NECUA2_12V_V2]  100.46 246.27 90 bottom
UNK5K12  UA2-12NJ-V2  [RL_NECUA2_12V_V2]  100.46 288.94 90 bottom
UNK5K13  UA2-12NJ-V2  [RL_NECUA2_12V_V2]  78.07 288.54 270 bottom
UNK5K14  UA2-12NJ-V2  [RL_NECUA2_12V_V2]  85.53 288.54 270 bottom
UNK5R1  4.7K-1-S4-WA  [R0402]  76.51 261.49 180 bottom
UNK5R2  3.01K-0.1-S4-PAN  [R0402]  96.73 308.78 270 bottom
UNK5R3  10K-0.1-S4  [R0402]  89.26 301.18 270 bottom
UNK5R7  1K-1-S4  [R0402]  76.75 325.55 180 bottom
UNK5R8  1K-1-S4  [R0402]  79.39 325.55 0 bottom
UNK5R13  0-5-S4  [R0402]  177.46 484.56 0 top
UNK5R14  0-5-S4  [R0402]  179.66 484.56 0 top
UNK5R41  24K-0.1-S4  [R0402]  74.26 308.78 270 bottom
UNK5R42  44.2K-0.1-S4-PAN  [R0402]  74.26 306.58 270 bottom
UNK5RS1  0-5-S4  [R0402]  82.12 268.76 0 bottom
UNK5RS2  NC/0-5-S4  [R0402]  89.39 273.05 270 bottom
UNK5RS3  NC/0-5-S4  [R0402]  82.12 270.03 0 bottom
UNK5RS4  0-5-S4  [R0402]  90.66 273.05 270 bottom
UNK5RS5  0-5-S4  [R0402]  90.02 274.7 0 bottom
UNK5SH2  SHORT  [DEFAULT_SHORT_SMALL]  206.1 483.17 0 top
UNK5SH7  SHORT  [DEFAULT_SHORT_SMALL]  236.95 483.17 0 top
UNK5SH9  SHORT  [DEFAULT_SHORT_SMALL]  239.15 483.17 0 top
UNK5SH14  SHORT  [DEFAULT_SHORT_SMALL]  201.69 483.17 0 top
UNK5SH16  SHORT  [DEFAULT_SHORT_SMALL]  203.9 483.17 0 top
UNK5SH20  SHORT  [DEFAULT_SHORT_SMALL]  208.3 483.17 0 top
UNK5SH29  SHORT  [DEFAULT_SHORT_SMALL]  210.51 483.17 0 top
UNK5SH30  SHORT  [DEFAULT_SHORT_SMALL]  212.71 483.17 0 top
UNK5SH32  SHORT  [DEFAULT_SHORT_SMALL]  214.91 483.17 0 top
UNK5SH33  SHORT  [DEFAULT_SHORT_SMALL]  217.12 483.17 0 top
UNK5SH34  SHORT  [DEFAULT_SHORT_SMALL]  219.32 483.17 0 top
UNK5SH35  SHORT  [DEFAULT_SHORT_SMALL]  221.52 483.17 0 top
UNK5SH36  SHORT  [DEFAULT_SHORT_SMALL]  223.73 483.17 0 top
UNK5SH37  SHORT  [DEFAULT_SHORT_SMALL]  225.93 483.17 0 top
UNK5SH38  SHORT  [DEFAULT_SHORT_SMALL]  228.13 483.17 0 top
UNK5SH39  SHORT  [DEFAULT_SHORT_SMALL]  230.34 483.17 0 top
UNK5SH40  SHORT  [DEFAULT_SHORT_SMALL]  232.54 483.17 0 top
UNK5SH41  SHORT  [DEFAULT_SHORT_SMALL]  234.74 483.17 0 top
UNK5TP_AVSS2/TST  TP01  [TP_040_T]  73.84 274.45 0 top
UNK5TP_GPIO0  TP01  [TP_040_T]  76.57 295.94 90 top
UNK5TP_GPIO1  TP01  [TP_040_T]  76.57 298.48 270 top
UNK5TP_GPIO2  TP01  [TP_040_T]  89.27 295.94 0 top
UNK5TP_GPIO3  TP01  [TP_040_T]  89.27 298.48 270 top
UNK5TP_GPIO4  TP01  [TP_040_T]  86.73 295.94 270 top
UNK5TP_LED0  TP01  [TP_040_T]  84.19 298.48 270 top
UNK5TP_LED1  TP01  [TP_040_T]  84.19 295.94 90 top
UNK5TP_LED2  TP01  [TP_040_T]  86.73 298.48 270 top
UNK5TP_LSIN1_F  TP01  [TP_040_T]  90.99 330.46 0 top
UNK5TP_LSIN1_G  TP01  [TP_040_T]  62.51 486.88 0 top
UNK5TP_LSIN1_S  TP01  [TP_040_T]  88.45 330.46 0 top
UNK5TP_LSIN2/NCHGEN_F  TP01  [TP_040_T]  90.99 335.54 0 top
UNK5TP_LSIN2/NCHGEN_G  TP01  [TP_040_T]  64.49 486.88 0 top
UNK5TP_LSIN2/NCHGEN_S  TP01  [TP_040_T]  88.45 335.54 0 top
UNK5TP_LSOUT1_F  TP01  [TP_040_T]  79.67 244.47 180 top
UNK5TP_LSOUT1_G  TP01  [TP_040_T]  66.47 486.88 0 top
UNK5TP_LSOUT1_S  TP01  [TP_040_T]  81.65 298.48 270 top
UNK5TP_LSOUT2/SUSPEND1_G  TP01  [TP_040_T]  68.45 486.88 0 top
UNK5TP_LSOUT2/SUSPEND1_S  TP01  [TP_040_T]  81.65 295.94 0 top
UNK5TP_LSOUT2/SUSPEND_F  TP01  [TP_040_T]  98.86 244.47 180 top
UNK5TP_NCHG/ATB0_F  TP01  [TP_040_T]  83.93 292.54 0 top
UNK5TP_NCHG/ATB0_G  TP01  [TP_040_T]  83.93 288.14 0 top
UNK5TP_NCHG/ATB0_S  TP01  [TP_040_T]  87.13 290.34 0 top
UNK5TP_NPG/ATB1_F  TP01  [TP_040_T]  76.47 292.54 0 top
UNK5TP_NPG/ATB1_G  TP01  [TP_040_T]  76.47 288.14 0 top
UNK5TP_NPG/ATB1_S  TP01  [TP_040_T]  79.67 292.54 0 top
UNK5TP_NTC  TP01  [TP_040_T]  91.4 307.08 180 top
UNK5TP_REF_5V  TP01  [TP_040_T]  94.59 242.27 180 top
UNK5TP_SCL  TP01  [TP_040_T]  76.47 330.46 0 top
UNK5TP_SDA  TP01  [TP_040_T]  79.67 330.46 0 top
UNK5TP_SHPHLD_F  TP01  [TP_040_T]  79.11 298.48 270 top
UNK5TP_SHPHLD_S  TP01  [TP_040_T]  79.11 295.94 90 top
UNK5TP_SW_F  TP01  [TP_040_T]  96.07 330.46 0 top
UNK5TP_SW_S  TP01  [TP_040_T]  93.53 330.46 0 top
UNK5TP_VBAT_F  TP01  [TP_040_T]  102.06 287.14 0 top
UNK5TP_VBAT_S  TP01  [TP_040_T]  98.86 287.14 0 top
UNK5TP_VBUS_F  TP01  [TP_040_T]  83.37 330.46 0 top
UNK5TP_VBUS_S  TP01  [TP_040_T]  85.91 330.46 0 top
UNK5TP_VDDIO_F  TP01  [TP_040_T]  98.61 335.54 0 top
UNK5TP_VDDIO_S  TP01  [TP_040_T]  70.43 486.88 0 top
UNK5TP_VEST  TP01  [TP_040_T]  73.28 269.26 0 top
UNK5TP_VOUT_F  TP01  [TP_040_T]  72.42 486.88 0 top
UNK5TP_VOUT_S  TP01  [TP_040_T]  98.61 330.46 0 top
UNK5TP_VSYS_F  TP01  [TP_040_T]  85.91 335.54 0 top
UNK5TP_VSYS_S  TP01  [TP_040_T]  83.37 335.54 0 top
UNK5U1  ADR4550BRZ-SOIC8  [SO8_195X127MM]  96.83 296.98 180 bottom
UNK6C1  1U-6.3-X7R-S6-MU  [C0603]  79.36 142.49 90 bottom
UNK6C2  2.2U-25-X8R-SA-TDK  [C1206]  95.84 178.21 180 bottom
UNK6C3  10U-6.3-X7R-S6-SS  [C0603]  91.92 177.36 270 bottom
UNK6C4  2.2U-25-X8R-SA-TDK  [C1206]  88.38 192.05 180 bottom
UNK6C5  2.2U-25-X8R-SA-TDK  [C1206]  82.68 192.05 0 bottom
UNK6C6  4.7U-6.3-X-S6  [C0603]  101.21 178.21 180 bottom
UNK6C7  0.1U-25-X7R-S6-YA  [C0603]  101.75 238.65 0 bottom
UNK6C8  1U-50-X7R-S6-TY  [C0603]  101.75 237.13 0 bottom
UNK6C9  0.1U-25-X7R-S6-YA  [C0603]  91.9 237.3 270 bottom
UNK6C12  2.2U-25-X8R-SA-TDK  [C1206]  86.98 142.89 90 bottom
UNK6CS1  CNC-S4  [C0402]  82.12 211.3 180 bottom
UNK6CS4  CNC-S4  [C0402]  82.12 207.49 0 bottom
UNK6CS5  CNC-S4  [C0402]  82.12 206.22 0 bottom
UNK6CS19  CNC-S4  [C0402]  95.85 207.02 0 bottom
UNK6CS20  CNC-S4  [C0402]  95.85 208.29 0 bottom
UNK6CS21  CNC-S4  [C0402]  95.85 209.56 0 bottom
UNK6CS22  CNC-S4  [C0402]  93.2 213.05 90 bottom
UNK6CS23  CNC-S4  [C0402]  91.93 213.05 90 bottom
UNK6CS25  CNC-S4  [C0402]  88.12 213.05 90 bottom
UNK6CS26  CNC-S4  [C0402]  86.85 213.05 270 bottom
UNK6CS27  CNC-S4  [C0402]  85.58 213.05 270 bottom
UNK6CS28  CNC-S4  [C0402]  84.31 213.05 90 bottom
UNK6K1  UA2-12NJ-V2  [RL_NECUA2_12V_V2]  92.99 185.33 90 bottom
UNK6K2  UA2-12NJ-V2  [RL_NECUA2_12V_V2]  85.53 185.33 90 bottom
UNK6K3  UA2-12NJ-V2  [RL_NECUA2_12V_V2]  76.66 207.46 270 bottom
UNK6K4  UA2-12NJ-V2  [RL_NECUA2_12V_V2]  85.53 169.7 90 bottom
UNK6K5  UA2-12NJ-V2  [RL_NECUA2_12V_V2]  78.07 169.7 90 bottom
UNK6K6  UA2-12NJ-V2  [RL_NECUA2_12V_V2]  92.99 169.3 270 bottom
UNK6K7  UA2-12NJ-V2  [RL_NECUA2_12V_V2]  100.46 169.7 90 bottom
UNK6K8  UA2-12NJ-V2  [RL_NECUA2_12V_V2]  78.07 185.33 90 bottom
UNK6K9  UA2-12NJ-V2  [RL_NECUA2_12V_V2]  100.46 142.72 270 bottom
UNK6K10  UA2-12NJ-V2  [RL_NECUA2_12V_V2]  100.46 185.33 90 bottom
UNK6K11  UA2-12NJ-V2  [RL_NECUA2_12V_V2]  92.99 229.98 90 bottom
UNK6K12  UA2-12NJ-V2  [RL_NECUA2_12V_V2]  100.46 229.98 90 bottom
UNK6K13  UA2-12NJ-V2  [RL_NECUA2_12V_V2]  78.07 229.58 270 bottom
UNK6K14  UA2-12NJ-V2  [RL_NECUA2_12V_V2]  85.53 229.58 270 bottom
UNK6R1  4.7K-1-S4-WA  [R0402]  76.51 201.49 180 bottom
UNK6R2  3.01K-0.1-S4-PAN  [R0402]  81.8 166.2 90 bottom
UNK6R3  10K-0.1-S4  [R0402]  89.26 172.8 270 bottom
UNK6R7  1K-1-S4  [R0402]  101.78 149.43 0 bottom
UNK6R8  1K-1-S4  [R0402]  99.14 149.43 180 bottom
UNK6R13  0-5-S4  [R0402]  181.87 484.56 0 top
UNK6R14  0-5-S4  [R0402]  184.07 484.56 0 top
UNK6R41  24K-0.1-S4  [R0402]  104.26 166.2 90 bottom
UNK6R42  44.2K-0.1-S4-PAN  [R0402]  104.26 168.4 90 bottom
UNK6RS1  0-5-S4  [R0402]  82.12 208.76 0 bottom
UNK6RS2  NC/0-5-S4  [R0402]  89.39 213.05 270 bottom
UNK6RS3  NC/0-5-S4  [R0402]  82.12 210.03 0 bottom
UNK6RS4  0-5-S4  [R0402]  90.66 213.05 270 bottom
UNK6RS5  0-5-S4  [R0402]  90.02 214.7 0 bottom
UNK6SH2  SHORT  [DEFAULT_SHORT_SMALL]  245.76 483.17 0 top
UNK6SH7  SHORT  [DEFAULT_SHORT_SMALL]  10.02 484.64 0 top
UNK6SH9  SHORT  [DEFAULT_SHORT_SMALL]  12.22 484.64 0 top
UNK6SH14  SHORT  [DEFAULT_SHORT_SMALL]  241.35 483.17 0 top
UNK6SH16  SHORT  [DEFAULT_SHORT_SMALL]  243.55 483.17 0 top
UNK6SH20  SHORT  [DEFAULT_SHORT_SMALL]  68.73 475.82 0 top
UNK6SH29  SHORT  [DEFAULT_SHORT_SMALL]  250.16 483.17 0 top
UNK6SH30  SHORT  [DEFAULT_SHORT_SMALL]  252.37 483.17 0 top
UNK6SH32  SHORT  [DEFAULT_SHORT_SMALL]  254.57 483.17 0 top
UNK6SH33  SHORT  [DEFAULT_SHORT_SMALL]  256.77 483.17 0 top
UNK6SH34  SHORT  [DEFAULT_SHORT_SMALL]  258.98 483.17 0 top
UNK6SH35  SHORT  [DEFAULT_SHORT_SMALL]  261.18 483.17 0 top
UNK6SH36  SHORT  [DEFAULT_SHORT_SMALL]  263.38 483.17 0 top
UNK6SH37  SHORT  [DEFAULT_SHORT_SMALL]  265.59 483.17 0 top
UNK6SH38  SHORT  [DEFAULT_SHORT_SMALL]  1.2 484.64 0 top
UNK6SH39  SHORT  [DEFAULT_SHORT_SMALL]  3.41 484.64 0 top
UNK6SH40  SHORT  [DEFAULT_SHORT_SMALL]  5.61 484.64 0 top
UNK6SH41  SHORT  [DEFAULT_SHORT_SMALL]  7.81 484.64 0 top
UNK6TP_AVSS2/TST  TP01  [TP_040_T]  73.84 214.45 0 top
UNK6TP_GPIO0  TP01  [TP_040_T]  89.17 178.59 270 top
UNK6TP_GPIO1  TP01  [TP_040_T]  89.17 176.05 90 top
UNK6TP_GPIO2  TP01  [TP_040_T]  76.47 178.59 180 top
UNK6TP_GPIO3  TP01  [TP_040_T]  76.47 176.05 90 top
UNK6TP_GPIO4  TP01  [TP_040_T]  79.01 178.59 90 top
UNK6TP_LED0  TP01  [TP_040_T]  81.55 176.05 90 top
UNK6TP_LED1  TP01  [TP_040_T]  81.55 178.59 270 top
UNK6TP_LED2  TP01  [TP_040_T]  79.01 176.05 90 top
UNK6TP_LSIN1_F  TP01  [TP_040_T]  86.98 146.72 180 top
UNK6TP_LSIN1_G  TP01  [TP_040_T]  74.4 486.88 0 top
UNK6TP_LSIN1_S  TP01  [TP_040_T]  89.52 146.72 180 top
UNK6TP_LSIN2/NCHGEN_F  TP01  [TP_040_T]  86.98 141.64 180 top
UNK6TP_LSIN2/NCHGEN_G  TP01  [TP_040_T]  76.38 486.88 0 top
UNK6TP_LSIN2/NCHGEN_S  TP01  [TP_040_T]  89.52 141.64 180 top
UNK6TP_LSOUT1_F  TP01  [TP_040_T]  78.36 486.88 0 top
UNK6TP_LSOUT1_G  TP01  [TP_040_T]  80.34 486.88 0 top
UNK6TP_LSOUT1_S  TP01  [TP_040_T]  84.09 176.05 90 top
UNK6TP_LSOUT2/SUSPEND1_G  TP01  [TP_040_T]  82.32 486.88 0 top
UNK6TP_LSOUT2/SUSPEND1_S  TP01  [TP_040_T]  84.09 178.59 180 top
UNK6TP_LSOUT2/SUSPEND_F  TP01  [TP_040_T]  84.3 486.88 0 top
UNK6TP_NCHG/ATB0_F  TP01  [TP_040_T]  83.93 233.58 0 top
UNK6TP_NCHG/ATB0_G  TP01  [TP_040_T]  83.93 229.18 0 top
UNK6TP_NCHG/ATB0_S  TP01  [TP_040_T]  87.13 231.38 0 top
UNK6TP_NPG/ATB1_F  TP01  [TP_040_T]  76.47 233.58 0 top
UNK6TP_NPG/ATB1_G  TP01  [TP_040_T]  76.47 229.18 0 top
UNK6TP_NPG/ATB1_S  TP01  [TP_040_T]  79.67 233.58 0 top
UNK6TP_NTC  TP01  [TP_040_T]  87.13 167.9 0 top
UNK6TP_REF_5V  TP01  [TP_040_T]  86.28 486.88 0 top
UNK6TP_SCL  TP01  [TP_040_T]  102.06 144.52 180 top
UNK6TP_SDA  TP01  [TP_040_T]  98.86 144.52 180 top
UNK6TP_SHPHLD_F  TP01  [TP_040_T]  86.63 176.05 90 top
UNK6TP_SHPHLD_S  TP01  [TP_040_T]  86.63 178.59 270 top
UNK6TP_SW_F  TP01  [TP_040_T]  81.9 146.72 180 top
UNK6TP_SW_S  TP01  [TP_040_T]  84.44 146.72 180 top
UNK6TP_VBAT_F  TP01  [TP_040_T]  102.06 228.18 0 top
UNK6TP_VBAT_S  TP01  [TP_040_T]  98.86 228.18 0 top
UNK6TP_VBUS_F  TP01  [TP_040_T]  94.6 146.72 180 top
UNK6TP_VBUS_S  TP01  [TP_040_T]  92.06 146.72 180 top
UNK6TP_VDDIO_F  TP01  [TP_040_T]  79.36 141.64 180 top
UNK6TP_VDDIO_S  TP01  [TP_040_T]  76.82 141.64 180 top
UNK6TP_VEST  TP01  [TP_040_T]  73.28 209.26 0 top
UNK6TP_VOUT_F  TP01  [TP_040_T]  76.82 146.72 180 top
UNK6TP_VOUT_S  TP01  [TP_040_T]  79.36 146.72 180 top
UNK6TP_VSYS_F  TP01  [TP_040_T]  92.06 141.64 180 top
UNK6TP_VSYS_S  TP01  [TP_040_T]  94.6 141.64 180 top
UNK6U1  ADR4550BRZ-SOIC8  [SO8_195X127MM]  96.32 238.02 180 bottom
UNK7C1  1U-6.3-X7R-S6-MU  [C0603]  128.61 334.69 270 bottom
UNK7C2  2.2U-25-X8R-SA-TDK  [C1206]  119.52 237.92 90 bottom
UNK7C3  10U-6.3-X7R-S6-SS  [C0603]  117.13 238.61 270 bottom
UNK7C4  2.2U-25-X8R-SA-TDK  [C1206]  109.67 237.92 90 bottom
UNK7C5  2.2U-25-X8R-SA-TDK  [C1206]  106.47 237.92 270 bottom
UNK7C6  4.7U-6.3-X-S6  [C0603]  134.26 241.42 270 bottom
UNK7C7  0.1U-25-X7R-S6-YA  [C0603]  132.25 297.61 0 bottom
UNK7C8  1U-50-X7R-S6-TY  [C0603]  132.25 296.09 0 bottom
UNK7C9  0.1U-25-X7R-S6-YA  [C0603]  122.41 296.26 270 bottom
UNK7C12  2.2U-25-X8R-SA-TDK  [C1206]  120.99 334.29 270 bottom
UNK7CS1  CNC-S4  [C0402]  112.12 271.3 180 bottom
UNK7CS4  CNC-S4  [C0402]  112.12 267.49 0 bottom
UNK7CS5  CNC-S4  [C0402]  112.12 266.22 0 bottom
UNK7CS19  CNC-S4  [C0402]  125.85 267.02 0 bottom
UNK7CS20  CNC-S4  [C0402]  125.85 268.29 0 bottom
UNK7CS21  CNC-S4  [C0402]  125.85 269.56 0 bottom
UNK7CS22  CNC-S4  [C0402]  123.2 273.05 90 bottom
UNK7CS23  CNC-S4  [C0402]  121.93 273.05 90 bottom
UNK7CS25  CNC-S4  [C0402]  118.12 273.05 90 bottom
UNK7CS26  CNC-S4  [C0402]  116.85 273.05 270 bottom
UNK7CS27  CNC-S4  [C0402]  115.58 273.05 270 bottom
UNK7CS28  CNC-S4  [C0402]  114.31 273.05 90 bottom
UNK7K1  UA2-12NJ-V2  [RL_NECUA2_12V_V2]  122.99 246.27 90 bottom
UNK7K2  UA2-12NJ-V2  [RL_NECUA2_12V_V2]  115.53 246.27 90 bottom
UNK7K3  UA2-12NJ-V2  [RL_NECUA2_12V_V2]  106.66 267.46 270 bottom
UNK7K4  UA2-12NJ-V2  [RL_NECUA2_12V_V2]  122.99 305.28 270 bottom
UNK7K5  UA2-12NJ-V2  [RL_NECUA2_12V_V2]  130.46 305.28 270 bottom
UNK7K6  UA2-12NJ-V2  [RL_NECUA2_12V_V2]  115.53 305.68 90 bottom
UNK7K7  UA2-12NJ-V2  [RL_NECUA2_12V_V2]  108.07 305.28 270 bottom
UNK7K8  UA2-12NJ-V2  [RL_NECUA2_12V_V2]  108.07 246.27 90 bottom
UNK7K9  UA2-12NJ-V2  [RL_NECUA2_12V_V2]  108.07 332.26 90 bottom
UNK7K10  UA2-12NJ-V2  [RL_NECUA2_12V_V2]  122.99 288.94 90 bottom
UNK7K11  UA2-12NJ-V2  [RL_NECUA2_12V_V2]  130.46 246.27 90 bottom
UNK7K12  UA2-12NJ-V2  [RL_NECUA2_12V_V2]  130.46 288.94 90 bottom
UNK7K13  UA2-12NJ-V2  [RL_NECUA2_12V_V2]  108.07 288.54 270 bottom
UNK7K14  UA2-12NJ-V2  [RL_NECUA2_12V_V2]  115.53 288.54 270 bottom
UNK7R1  4.7K-1-S4-WA  [R0402]  106.51 261.49 180 bottom
UNK7R2  3.01K-0.1-S4-PAN  [R0402]  126.73 308.78 270 bottom
UNK7R3  10K-0.1-S4  [R0402]  119.26 301.18 270 bottom
UNK7R7  1K-1-S4  [R0402]  106.75 325.55 180 bottom
UNK7R8  1K-1-S4  [R0402]  109.39 325.55 0 bottom
UNK7R13  0-5-S4  [R0402]  186.27 484.56 0 top
UNK7R14  0-5-S4  [R0402]  188.47 484.56 0 top
UNK7R41  24K-0.1-S4  [R0402]  104.26 308.78 270 bottom
UNK7R42  44.2K-0.1-S4-PAN  [R0402]  104.26 306.58 270 bottom
UNK7RS1  0-5-S4  [R0402]  112.12 268.76 0 bottom
UNK7RS2  NC/0-5-S4  [R0402]  119.39 273.05 270 bottom
UNK7RS3  NC/0-5-S4  [R0402]  112.12 270.03 0 bottom
UNK7RS4  0-5-S4  [R0402]  120.66 273.05 270 bottom
UNK7RS5  0-5-S4  [R0402]  120.02 274.7 0 bottom
UNK7SH2  SHORT  [DEFAULT_SHORT_SMALL]  18.83 484.64 0 top
UNK7SH7  SHORT  [DEFAULT_SHORT_SMALL]  49.67 484.64 0 top
UNK7SH9  SHORT  [DEFAULT_SHORT_SMALL]  51.88 484.64 0 top
UNK7SH14  SHORT  [DEFAULT_SHORT_SMALL]  14.42 484.64 0 top
UNK7SH16  SHORT  [DEFAULT_SHORT_SMALL]  16.63 484.64 0 top
UNK7SH20  SHORT  [DEFAULT_SHORT_SMALL]  21.03 484.64 0 top
UNK7SH29  SHORT  [DEFAULT_SHORT_SMALL]  23.24 484.64 0 top
UNK7SH30  SHORT  [DEFAULT_SHORT_SMALL]  25.44 484.64 0 top
UNK7SH32  SHORT  [DEFAULT_SHORT_SMALL]  27.64 484.64 0 top
UNK7SH33  SHORT  [DEFAULT_SHORT_SMALL]  29.84 484.64 0 top
UNK7SH34  SHORT  [DEFAULT_SHORT_SMALL]  32.05 484.64 0 top
UNK7SH35  SHORT  [DEFAULT_SHORT_SMALL]  34.25 484.64 0 top
UNK7SH36  SHORT  [DEFAULT_SHORT_SMALL]  36.45 484.64 0 top
UNK7SH37  SHORT  [DEFAULT_SHORT_SMALL]  38.66 484.64 0 top
UNK7SH38  SHORT  [DEFAULT_SHORT_SMALL]  40.86 484.64 0 top
UNK7SH39  SHORT  [DEFAULT_SHORT_SMALL]  43.06 484.64 0 top
UNK7SH40  SHORT  [DEFAULT_SHORT_SMALL]  45.27 484.64 0 top
UNK7SH41  SHORT  [DEFAULT_SHORT_SMALL]  47.47 484.64 0 top
UNK7TP_AVSS2/TST  TP01  [TP_040_T]  103.84 274.45 0 top
UNK7TP_GPIO0  TP01  [TP_040_T]  106.57 295.94 90 top
UNK7TP_GPIO1  TP01  [TP_040_T]  106.57 298.48 270 top
UNK7TP_GPIO2  TP01  [TP_040_T]  119.27 295.94 0 top
UNK7TP_GPIO3  TP01  [TP_040_T]  119.27 298.48 270 top
UNK7TP_GPIO4  TP01  [TP_040_T]  116.73 295.94 270 top
UNK7TP_LED0  TP01  [TP_040_T]  114.19 298.48 270 top
UNK7TP_LED1  TP01  [TP_040_T]  114.19 295.94 90 top
UNK7TP_LED2  TP01  [TP_040_T]  116.73 298.48 270 top
UNK7TP_LSIN1_F  TP01  [TP_040_T]  120.99 330.46 0 top
UNK7TP_LSIN1_G  TP01  [TP_040_T]  88.27 486.88 0 top
UNK7TP_LSIN1_S  TP01  [TP_040_T]  118.45 330.46 0 top
UNK7TP_LSIN2/NCHGEN_F  TP01  [TP_040_T]  120.99 335.54 0 top
UNK7TP_LSIN2/NCHGEN_G  TP01  [TP_040_T]  90.25 486.88 0 top
UNK7TP_LSIN2/NCHGEN_S  TP01  [TP_040_T]  118.45 335.54 0 top
UNK7TP_LSOUT1_F  TP01  [TP_040_T]  109.67 244.47 180 top
UNK7TP_LSOUT1_G  TP01  [TP_040_T]  92.23 486.88 0 top
UNK7TP_LSOUT1_S  TP01  [TP_040_T]  111.65 298.48 270 top
UNK7TP_LSOUT2/SUSPEND1_G  TP01  [TP_040_T]  94.21 486.88 0 top
UNK7TP_LSOUT2/SUSPEND1_S  TP01  [TP_040_T]  111.65 295.94 0 top
UNK7TP_LSOUT2/SUSPEND_F  TP01  [TP_040_T]  128.86 244.47 180 top
UNK7TP_NCHG/ATB0_F  TP01  [TP_040_T]  113.93 292.54 0 top
UNK7TP_NCHG/ATB0_G  TP01  [TP_040_T]  113.93 288.14 0 top
UNK7TP_NCHG/ATB0_S  TP01  [TP_040_T]  117.13 290.34 0 top
UNK7TP_NPG/ATB1_F  TP01  [TP_040_T]  106.47 292.54 0 top
UNK7TP_NPG/ATB1_G  TP01  [TP_040_T]  106.47 288.14 0 top
UNK7TP_NPG/ATB1_S  TP01  [TP_040_T]  109.67 292.54 0 top
UNK7TP_NTC  TP01  [TP_040_T]  121.39 307.08 180 top
UNK7TP_REF_5V  TP01  [TP_040_T]  124.59 242.27 180 top
UNK7TP_SCL  TP01  [TP_040_T]  106.47 330.46 0 top
UNK7TP_SDA  TP01  [TP_040_T]  109.67 330.46 0 top
UNK7TP_SHPHLD_F  TP01  [TP_040_T]  109.11 298.48 270 top
UNK7TP_SHPHLD_S  TP01  [TP_040_T]  109.11 295.94 90 top
UNK7TP_SW_F  TP01  [TP_040_T]  126.07 330.46 0 top
UNK7TP_SW_S  TP01  [TP_040_T]  123.53 330.46 0 top
UNK7TP_VBAT_F  TP01  [TP_040_T]  132.06 287.14 0 top
UNK7TP_VBAT_S  TP01  [TP_040_T]  128.86 287.14 0 top
UNK7TP_VBUS_F  TP01  [TP_040_T]  113.37 330.46 0 top
UNK7TP_VBUS_S  TP01  [TP_040_T]  115.91 330.46 0 top
UNK7TP_VDDIO_F  TP01  [TP_040_T]  128.61 335.54 0 top
UNK7TP_VDDIO_S  TP01  [TP_040_T]  96.19 486.88 0 top
UNK7TP_VEST  TP01  [TP_040_T]  103.28 269.26 0 top
UNK7TP_VOUT_F  TP01  [TP_040_T]  98.17 486.88 0 top
UNK7TP_VOUT_S  TP01  [TP_040_T]  128.61 330.46 0 top
UNK7TP_VSYS_F  TP01  [TP_040_T]  115.91 335.54 0 top
UNK7TP_VSYS_S  TP01  [TP_040_T]  113.37 335.54 0 top
UNK7U1  ADR4550BRZ-SOIC8  [SO8_195X127MM]  126.83 296.98 180 bottom
UNK8C1  1U-6.3-X7R-S6-MU  [C0603]  109.36 142.49 90 bottom
UNK8C2  2.2U-25-X8R-SA-TDK  [C1206]  125.84 178.21 180 bottom
UNK8C3  10U-6.3-X7R-S6-SS  [C0603]  121.92 177.36 270 bottom
UNK8C4  2.2U-25-X8R-SA-TDK  [C1206]  118.38 192.05 180 bottom
UNK8C5  2.2U-25-X8R-SA-TDK  [C1206]  112.68 192.05 0 bottom
UNK8C6  4.7U-6.3-X-S6  [C0603]  131.21 178.21 180 bottom
UNK8C7  0.1U-25-X7R-S6-YA  [C0603]  131.75 238.65 0 bottom
UNK8C8  1U-50-X7R-S6-TY  [C0603]  131.75 237.13 0 bottom
UNK8C9  0.1U-25-X7R-S6-YA  [C0603]  121.9 237.3 270 bottom
UNK8C12  2.2U-25-X8R-SA-TDK  [C1206]  116.98 142.89 90 bottom
UNK8CS1  CNC-S4  [C0402]  112.12 211.3 180 bottom
UNK8CS4  CNC-S4  [C0402]  112.12 207.49 0 bottom
UNK8CS5  CNC-S4  [C0402]  112.12 206.22 0 bottom
UNK8CS19  CNC-S4  [C0402]  125.85 207.02 0 bottom
UNK8CS20  CNC-S4  [C0402]  125.85 208.29 0 bottom
UNK8CS21  CNC-S4  [C0402]  125.85 209.56 0 bottom
UNK8CS22  CNC-S4  [C0402]  123.2 213.05 90 bottom
UNK8CS23  CNC-S4  [C0402]  121.93 213.05 90 bottom
UNK8CS25  CNC-S4  [C0402]  118.12 213.05 90 bottom
UNK8CS26  CNC-S4  [C0402]  116.85 213.05 270 bottom
UNK8CS27  CNC-S4  [C0402]  115.58 213.05 270 bottom
UNK8CS28  CNC-S4  [C0402]  114.31 213.05 90 bottom
UNK8K1  UA2-12NJ-V2  [RL_NECUA2_12V_V2]  122.99 185.33 90 bottom
UNK8K2  UA2-12NJ-V2  [RL_NECUA2_12V_V2]  115.53 185.33 90 bottom
UNK8K3  UA2-12NJ-V2  [RL_NECUA2_12V_V2]  106.66 207.46 270 bottom
UNK8K4  UA2-12NJ-V2  [RL_NECUA2_12V_V2]  115.53 169.7 90 bottom
UNK8K5  UA2-12NJ-V2  [RL_NECUA2_12V_V2]  108.07 169.7 90 bottom
UNK8K6  UA2-12NJ-V2  [RL_NECUA2_12V_V2]  122.99 169.3 270 bottom
UNK8K7  UA2-12NJ-V2  [RL_NECUA2_12V_V2]  130.46 169.7 90 bottom
UNK8K8  UA2-12NJ-V2  [RL_NECUA2_12V_V2]  108.07 185.33 90 bottom
UNK8K9  UA2-12NJ-V2  [RL_NECUA2_12V_V2]  130.46 142.72 270 bottom
UNK8K10  UA2-12NJ-V2  [RL_NECUA2_12V_V2]  130.46 185.33 90 bottom
UNK8K11  UA2-12NJ-V2  [RL_NECUA2_12V_V2]  122.99 229.98 90 bottom
UNK8K12  UA2-12NJ-V2  [RL_NECUA2_12V_V2]  130.46 229.98 90 bottom
UNK8K13  UA2-12NJ-V2  [RL_NECUA2_12V_V2]  108.07 229.58 270 bottom
UNK8K14  UA2-12NJ-V2  [RL_NECUA2_12V_V2]  115.53 229.58 270 bottom
UNK8R1  4.7K-1-S4-WA  [R0402]  106.51 201.49 180 bottom
UNK8R2  3.01K-0.1-S4-PAN  [R0402]  111.8 166.2 90 bottom
UNK8R3  10K-0.1-S4  [R0402]  119.26 172.8 270 bottom
UNK8R7  1K-1-S4  [R0402]  131.78 149.43 0 bottom
UNK8R8  1K-1-S4  [R0402]  129.14 149.43 180 bottom
UNK8R13  0-5-S4  [R0402]  190.68 484.56 0 top
UNK8R14  0-5-S4  [R0402]  192.88 484.56 0 top
UNK8R41  24K-0.1-S4  [R0402]  134.26 166.2 90 bottom
UNK8R42  44.2K-0.1-S4-PAN  [R0402]  134.26 168.4 90 bottom
UNK8RS1  0-5-S4  [R0402]  112.12 208.76 0 bottom
UNK8RS2  NC/0-5-S4  [R0402]  119.39 213.05 270 bottom
UNK8RS3  NC/0-5-S4  [R0402]  112.12 210.03 0 bottom
UNK8RS4  0-5-S4  [R0402]  120.66 213.05 270 bottom
UNK8RS5  0-5-S4  [R0402]  120.02 214.7 0 bottom
UNK8SH2  SHORT  [DEFAULT_SHORT_SMALL]  58.49 484.64 0 top
UNK8SH7  SHORT  [DEFAULT_SHORT_SMALL]  89.33 484.64 0 top
UNK8SH9  SHORT  [DEFAULT_SHORT_SMALL]  91.53 484.64 0 top
UNK8SH14  SHORT  [DEFAULT_SHORT_SMALL]  54.08 484.64 0 top
UNK8SH16  SHORT  [DEFAULT_SHORT_SMALL]  56.28 484.64 0 top
UNK8SH20  SHORT  [DEFAULT_SHORT_SMALL]  60.69 484.64 0 top
UNK8SH29  SHORT  [DEFAULT_SHORT_SMALL]  62.89 484.64 0 top
UNK8SH30  SHORT  [DEFAULT_SHORT_SMALL]  65.1 484.64 0 top
UNK8SH32  SHORT  [DEFAULT_SHORT_SMALL]  67.3 484.64 0 top
UNK8SH33  SHORT  [DEFAULT_SHORT_SMALL]  69.5 484.64 0 top
UNK8SH34  SHORT  [DEFAULT_SHORT_SMALL]  71.71 484.64 0 top
UNK8SH35  SHORT  [DEFAULT_SHORT_SMALL]  73.91 484.64 0 top
UNK8SH36  SHORT  [DEFAULT_SHORT_SMALL]  76.11 484.64 0 top
UNK8SH37  SHORT  [DEFAULT_SHORT_SMALL]  78.32 484.64 0 top
UNK8SH38  SHORT  [DEFAULT_SHORT_SMALL]  80.52 484.64 0 top
UNK8SH39  SHORT  [DEFAULT_SHORT_SMALL]  82.72 484.64 0 top
UNK8SH40  SHORT  [DEFAULT_SHORT_SMALL]  84.92 484.64 0 top
UNK8SH41  SHORT  [DEFAULT_SHORT_SMALL]  87.13 484.64 0 top
UNK8TP_AVSS2/TST  TP01  [TP_040_T]  103.84 214.45 0 top
UNK8TP_GPIO0  TP01  [TP_040_T]  119.17 178.59 270 top
UNK8TP_GPIO1  TP01  [TP_040_T]  119.17 176.05 90 top
UNK8TP_GPIO2  TP01  [TP_040_T]  106.47 178.59 180 top
UNK8TP_GPIO3  TP01  [TP_040_T]  106.47 176.05 90 top
UNK8TP_GPIO4  TP01  [TP_040_T]  109.01 178.59 90 top
UNK8TP_LED0  TP01  [TP_040_T]  111.55 176.05 90 top
UNK8TP_LED1  TP01  [TP_040_T]  111.55 178.59 270 top
UNK8TP_LED2  TP01  [TP_040_T]  109.01 176.05 90 top
UNK8TP_LSIN1_F  TP01  [TP_040_T]  116.98 146.72 180 top
UNK8TP_LSIN1_G  TP01  [TP_040_T]  100.15 486.88 0 top
UNK8TP_LSIN1_S  TP01  [TP_040_T]  119.52 146.72 180 top
UNK8TP_LSIN2/NCHGEN_F  TP01  [TP_040_T]  116.98 141.64 180 top
UNK8TP_LSIN2/NCHGEN_G  TP01  [TP_040_T]  102.13 486.88 0 top
UNK8TP_LSIN2/NCHGEN_S  TP01  [TP_040_T]  119.52 141.64 180 top
UNK8TP_LSOUT1_F  TP01  [TP_040_T]  104.11 486.88 0 top
UNK8TP_LSOUT1_G  TP01  [TP_040_T]  106.1 486.88 0 top
UNK8TP_LSOUT1_S  TP01  [TP_040_T]  114.09 176.05 90 top
UNK8TP_LSOUT2/SUSPEND1_G  TP01  [TP_040_T]  108.08 486.88 0 top
UNK8TP_LSOUT2/SUSPEND1_S  TP01  [TP_040_T]  114.09 178.59 180 top
UNK8TP_LSOUT2/SUSPEND_F  TP01  [TP_040_T]  110.06 486.88 0 top
UNK8TP_NCHG/ATB0_F  TP01  [TP_040_T]  113.93 233.58 0 top
UNK8TP_NCHG/ATB0_G  TP01  [TP_040_T]  113.93 229.18 0 top
UNK8TP_NCHG/ATB0_S  TP01  [TP_040_T]  117.13 231.38 0 top
UNK8TP_NPG/ATB1_F  TP01  [TP_040_T]  106.47 233.58 0 top
UNK8TP_NPG/ATB1_G  TP01  [TP_040_T]  106.47 229.18 0 top
UNK8TP_NPG/ATB1_S  TP01  [TP_040_T]  109.67 233.58 0 top
UNK8TP_NTC  TP01  [TP_040_T]  117.13 167.9 0 top
UNK8TP_REF_5V  TP01  [TP_040_T]  112.04 486.88 0 top
UNK8TP_SCL  TP01  [TP_040_T]  132.06 144.52 180 top
UNK8TP_SDA  TP01  [TP_040_T]  128.86 144.52 180 top
UNK8TP_SHPHLD_F  TP01  [TP_040_T]  116.63 176.05 90 top
UNK8TP_SHPHLD_S  TP01  [TP_040_T]  116.63 178.59 270 top
UNK8TP_SW_F  TP01  [TP_040_T]  111.9 146.72 180 top
UNK8TP_SW_S  TP01  [TP_040_T]  114.44 146.72 180 top
UNK8TP_VBAT_F  TP01  [TP_040_T]  132.06 228.18 0 top
UNK8TP_VBAT_S  TP01  [TP_040_T]  128.86 228.18 0 top
UNK8TP_VBUS_F  TP01  [TP_040_T]  124.6 146.72 180 top
UNK8TP_VBUS_S  TP01  [TP_040_T]  122.06 146.72 180 top
UNK8TP_VDDIO_F  TP01  [TP_040_T]  109.36 141.64 180 top
UNK8TP_VDDIO_S  TP01  [TP_040_T]  106.82 141.64 180 top
UNK8TP_VEST  TP01  [TP_040_T]  103.28 209.26 0 top
UNK8TP_VOUT_F  TP01  [TP_040_T]  106.82 146.72 180 top
UNK8TP_VOUT_S  TP01  [TP_040_T]  109.36 146.72 180 top
UNK8TP_VSYS_F  TP01  [TP_040_T]  122.06 141.64 180 top
UNK8TP_VSYS_S  TP01  [TP_040_T]  124.6 141.64 180 top
UNK8U1  ADR4550BRZ-SOIC8  [SO8_195X127MM]  126.32 238.02 180 bottom
UNK9C1  1U-6.3-X7R-S6-MU  [C0603]  158.61 334.69 270 bottom
UNK9C2  2.2U-25-X8R-SA-TDK  [C1206]  149.52 237.92 90 bottom
UNK9C3  10U-6.3-X7R-S6-SS  [C0603]  147.13 238.61 270 bottom
UNK9C4  2.2U-25-X8R-SA-TDK  [C1206]  139.67 237.92 90 bottom
UNK9C5  2.2U-25-X8R-SA-TDK  [C1206]  136.47 237.92 270 bottom
UNK9C6  4.7U-6.3-X-S6  [C0603]  164.26 241.42 270 bottom
UNK9C7  0.1U-25-X7R-S6-YA  [C0603]  162.25 297.61 0 bottom
UNK9C8  1U-50-X7R-S6-TY  [C0603]  162.25 296.09 0 bottom
UNK9C9  0.1U-25-X7R-S6-YA  [C0603]  152.41 296.26 270 bottom
UNK9C12  2.2U-25-X8R-SA-TDK  [C1206]  150.99 334.29 270 bottom
UNK9CS1  CNC-S4  [C0402]  142.12 271.3 180 bottom
UNK9CS4  CNC-S4  [C0402]  142.12 267.49 0 bottom
UNK9CS5  CNC-S4  [C0402]  142.12 266.22 0 bottom
UNK9CS19  CNC-S4  [C0402]  155.85 267.02 0 bottom
UNK9CS20  CNC-S4  [C0402]  155.85 268.29 0 bottom
UNK9CS21  CNC-S4  [C0402]  155.85 269.56 0 bottom
UNK9CS22  CNC-S4  [C0402]  153.2 273.05 90 bottom
UNK9CS23  CNC-S4  [C0402]  151.93 273.05 90 bottom
UNK9CS25  CNC-S4  [C0402]  148.12 273.05 90 bottom
UNK9CS26  CNC-S4  [C0402]  146.85 273.05 270 bottom
UNK9CS27  CNC-S4  [C0402]  145.58 273.05 270 bottom
UNK9CS28  CNC-S4  [C0402]  144.31 273.05 90 bottom
UNK9K1  UA2-12NJ-V2  [RL_NECUA2_12V_V2]  152.99 246.27 90 bottom
UNK9K2  UA2-12NJ-V2  [RL_NECUA2_12V_V2]  145.53 246.27 90 bottom
UNK9K3  UA2-12NJ-V2  [RL_NECUA2_12V_V2]  136.66 267.46 270 bottom
UNK9K4  UA2-12NJ-V2  [RL_NECUA2_12V_V2]  152.99 305.28 270 bottom
UNK9K5  UA2-12NJ-V2  [RL_NECUA2_12V_V2]  160.46 305.28 270 bottom
UNK9K6  UA2-12NJ-V2  [RL_NECUA2_12V_V2]  145.53 305.68 90 bottom
UNK9K7  UA2-12NJ-V2  [RL_NECUA2_12V_V2]  138.07 305.28 270 bottom
UNK9K8  UA2-12NJ-V2  [RL_NECUA2_12V_V2]  138.07 246.27 90 bottom
UNK9K9  UA2-12NJ-V2  [RL_NECUA2_12V_V2]  138.07 332.26 90 bottom
UNK9K10  UA2-12NJ-V2  [RL_NECUA2_12V_V2]  152.99 288.94 90 bottom
UNK9K11  UA2-12NJ-V2  [RL_NECUA2_12V_V2]  160.46 246.27 90 bottom
UNK9K12  UA2-12NJ-V2  [RL_NECUA2_12V_V2]  160.46 288.94 90 bottom
UNK9K13  UA2-12NJ-V2  [RL_NECUA2_12V_V2]  138.07 288.54 270 bottom
UNK9K14  UA2-12NJ-V2  [RL_NECUA2_12V_V2]  145.53 288.54 270 bottom
UNK9R1  4.7K-1-S4-WA  [R0402]  136.51 261.49 180 bottom
UNK9R2  3.01K-0.1-S4-PAN  [R0402]  156.73 308.78 270 bottom
UNK9R3  10K-0.1-S4  [R0402]  149.26 301.18 270 bottom
UNK9R7  1K-1-S4  [R0402]  136.75 325.55 180 bottom
UNK9R8  1K-1-S4  [R0402]  139.39 325.55 0 bottom
UNK9R13  0-5-S4  [R0402]  195.08 484.56 0 top
UNK9R14  0-5-S4  [R0402]  247.96 483.08 0 top
UNK9R41  24K-0.1-S4  [R0402]  134.26 308.78 270 bottom
UNK9R42  44.2K-0.1-S4-PAN  [R0402]  134.26 306.58 270 bottom
UNK9RS1  0-5-S4  [R0402]  142.12 268.76 0 bottom
UNK9RS2  NC/0-5-S4  [R0402]  149.39 273.05 270 bottom
UNK9RS3  NC/0-5-S4  [R0402]  142.12 270.03 0 bottom
UNK9RS4  0-5-S4  [R0402]  150.66 273.05 270 bottom
UNK9RS5  0-5-S4  [R0402]  150.02 274.7 0 bottom
UNK9SH2  SHORT  [DEFAULT_SHORT_SMALL]  98.14 484.64 0 top
UNK9SH7  SHORT  [DEFAULT_SHORT_SMALL]  128.99 484.64 0 top
UNK9SH9  SHORT  [DEFAULT_SHORT_SMALL]  131.19 484.64 0 top
UNK9SH14  SHORT  [DEFAULT_SHORT_SMALL]  93.74 484.64 0 top
UNK9SH16  SHORT  [DEFAULT_SHORT_SMALL]  95.94 484.64 0 top
UNK9SH20  SHORT  [DEFAULT_SHORT_SMALL]  100.35 484.64 0 top
UNK9SH29  SHORT  [DEFAULT_SHORT_SMALL]  102.55 484.64 0 top
UNK9SH30  SHORT  [DEFAULT_SHORT_SMALL]  104.75 484.64 0 top
UNK9SH32  SHORT  [DEFAULT_SHORT_SMALL]  106.96 484.64 0 top
UNK9SH33  SHORT  [DEFAULT_SHORT_SMALL]  109.16 484.64 0 top
UNK9SH34  SHORT  [DEFAULT_SHORT_SMALL]  111.36 484.64 0 top
UNK9SH35  SHORT  [DEFAULT_SHORT_SMALL]  113.57 484.64 0 top
UNK9SH36  SHORT  [DEFAULT_SHORT_SMALL]  115.77 484.64 0 top
UNK9SH37  SHORT  [DEFAULT_SHORT_SMALL]  117.97 484.64 0 top
